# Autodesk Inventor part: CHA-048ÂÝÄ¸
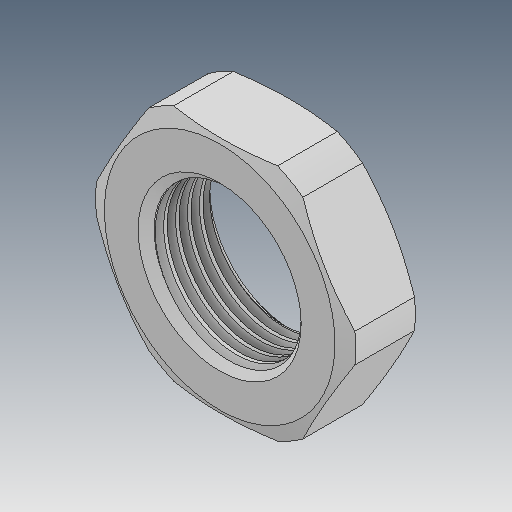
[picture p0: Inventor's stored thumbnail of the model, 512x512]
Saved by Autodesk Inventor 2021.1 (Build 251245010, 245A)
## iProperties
Created: 2019-05
Part Number: CHA-048ÂÝÄ¸
Material: Ogólny
Document SubType Name: Modeling
Designer: user
Density: 1 g/cm^3
Appearance: Domyślna
Author: user
Revision Number: ÈÎºÎ
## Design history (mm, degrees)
feature "¾µÏò1"
node "Bryła1"
